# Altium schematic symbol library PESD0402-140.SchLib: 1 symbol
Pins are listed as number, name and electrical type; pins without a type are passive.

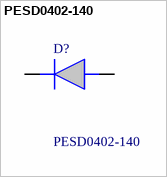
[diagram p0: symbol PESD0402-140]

## PESD0402-140
designator D?
TVS Diode Bi-Directional PESD0402-140 40V, SOD-923 2-Pin; Manufacturer_Name: TE Connectivity; Geometry.Height: 0.43mm
footprint DIONC1005X43N
pins: 1 K, 2 A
